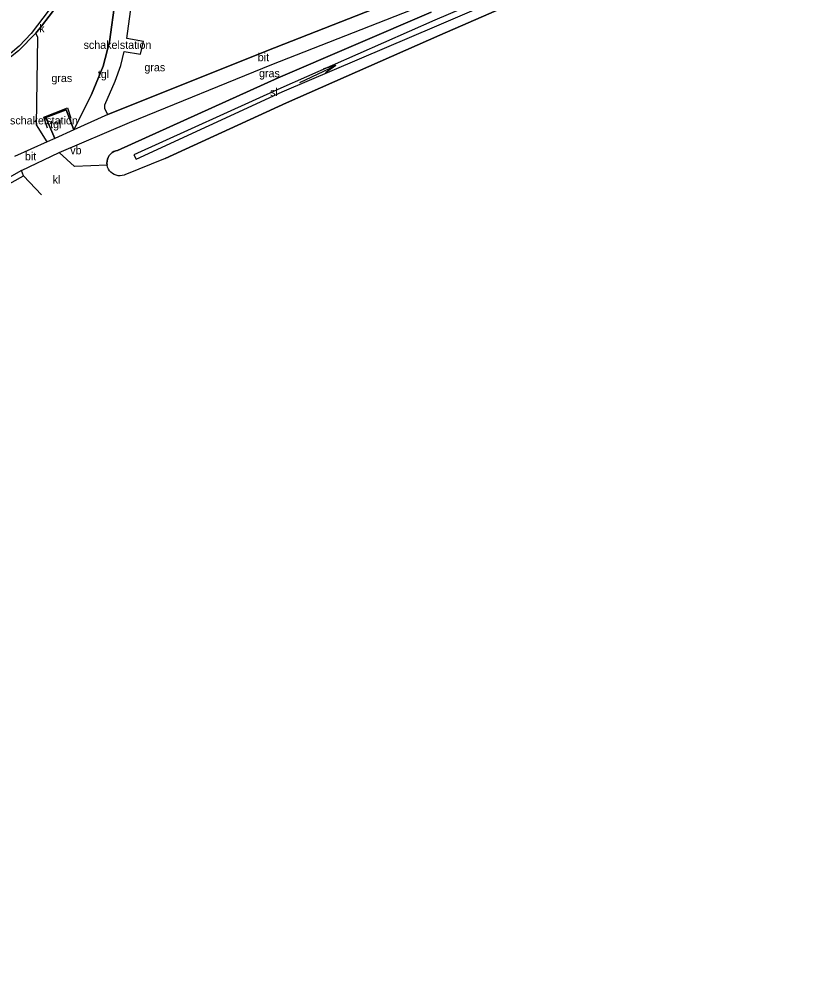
# Model space of a CAD drawing. Extents: x 154825 to 158680, y 370717 to 378075.
# Drawn here: x 156908.2 to 157007.2, y 372365.6 to 372483.5 of the extents above; entities that cross this region are included whole.
import ezdxf

# ---------------------------------------------------------------- set-up
doc = ezdxf.new("R2010")
doc.units = 0
for name, color, linetype in [('bitumenverharding(vs)', 7, 'Continuous'), ('grazige vegetatie(vs)', 7, 'Continuous'), ('hekwerkinsteek', 7, 'Continuous'), ('insteek sloot', 7, 'Continuous'), ('kantstreep', 7, 'Continuous'), ('klinkerverharding(vs)', 7, 'Continuous'), ('kolk', 7, 'Continuous'), ('maaiveldlijn algemeen - gesloten verharding', 7, 'Continuous'), ('maaiveldlijn algemeen - verharding algemeen', 7, 'Continuous'), ('palenrij', 7, 'Continuous'), ('schakelstation(vs)', 7, 'Continuous'), ('Sloot bodem', 7, 'Continuous'), ('sloot(vs)', 7, 'Continuous'), ('stroomrichting  watergangen', 7, 'Continuous'), ('tegelverh(vs)', 7, 'Continuous'), ('verkeersb_z kabel', 7, 'Continuous'), ('vlak_Grazige_vegetatie', 7, 'Continuous')]:
    doc.layers.add(name, color=color, linetype=linetype)

msp = doc.modelspace()

# ---------------------------------------------------------------- linework, layer by layer
at = {"layer": 'hekwerkinsteek'}
msp.add_lwpolyline([(156926.48, 372466.07), (156941.63, 372473), (156960.78, 372481.46), (156976.59, 372488.39), (156983.26, 372491.21)], dxfattribs=at)
at = {"layer": 'insteek sloot'}
msp.add_lwpolyline([(156926.48, 372466.07), (156921.43, 372464.01), (156921.35, 372463.98), (156921.11, 372463.91), (156920.86, 372463.88), (156920.61, 372463.9), (156920.36, 372463.95), (156920.12, 372464.04), (156919.9, 372464.17), (156919.71, 372464.33), (156919.54, 372464.52), (156919.4, 372464.73), (156919.3, 372464.96), (156919.23, 372465.21), (156919.21, 372465.46), (156919.22, 372465.71), (156919.28, 372465.96), (156919.37, 372466.19), (156919.5, 372466.41), (156919.66, 372466.61), (156919.85, 372466.78), (156920.06, 372466.91), (156920.3, 372467.01), (156920.54, 372467.07), (156940.59, 372476.12), (156959.72, 372484.32)], dxfattribs=at)
at = {"layer": 'kantstreep'}
msp.add_lwpolyline([(156912, 372484.63), (156909.76, 372481.66), (156908.24, 372480.1), (156906.59, 372478.67), (156904.7, 372477.42), (156902.73, 372476.3), (156901.13, 372475.39), (156899.83, 372474.44), (156898.3, 372472.87), (156897.08, 372471.22), (156894.54, 372467.02), (156892.73, 372464.17), (156889.8, 372459.96), (156887.24, 372457.64), (156884.63, 372455.47), (156876.12, 372449.06)], dxfattribs=at)
at = {"layer": 'maaiveldlijn algemeen - gesloten verharding'}
for points in [[(156919.34, 372471.53), (156939.19, 372479.51), (156958.63, 372487.15), (156986.56, 372498.21), (157006.17, 372506)], [(156913.23, 372466.8), (156922.02, 372470.54), (156939.79, 372477.79), (156959.27, 372485.43), (156987.12, 372496.58), (157007.18, 372504.38)], [(156920.47, 372488.95), (156918.9, 372488.58), (156916.79, 372487.72), (156914.53, 372486.34), (156912.93, 372485.08), (156911.05, 372482.6), (156910.32, 372481.71)], [(156910.32, 372481.71), (156908.15, 372479.51), (156906.33, 372478.04), (156904.02, 372476.62), (156901.44, 372475.19)], [(156919.34, 372471.53), (156915.07, 372469.64)], [(156915.07, 372469.64), (156912.68, 372468.55)], [(156911.73, 372468.12), (156907.65, 372466.29)], [(156912.68, 372468.55), (156911.73, 372468.12)], [(156908.52, 372464.53), (156913.23, 372466.8)], [(156908.52, 372464.53), (156898.44, 372458.84), (156897.09, 372458.03), (156894.3, 372456.31), (156889.29, 372453.07), (156884.66, 372450.07), (156874.8, 372442.6), (156871.75, 372440.11), (156866.81, 372435.59), (156866.44, 372435.25), (156862.3, 372431.22), (156854.27, 372423.1), (156846.87, 372414.74), (156841.18, 372407.59), (156835.27, 372399.43), (156829.96, 372390.65), (156826.51, 372382.86), (156819.22, 372365.62)]]:
    msp.add_lwpolyline(points, dxfattribs=at)
at = {"layer": 'maaiveldlijn algemeen - verharding algemeen'}
for points in [[(156919.34, 372471.53), (156918.96, 372472.26), (156918.96, 372472.74), (156920.22, 372475.71), (156920.94, 372477.68), (156921.37, 372479.44), (156923.41, 372479.09), (156923.77, 372480.68), (156921.7, 372481.03), (156922.52, 372487.22), (156922.5, 372489.42)], [(156915.07, 372469.64), (156917.26, 372474.06), (156918.73, 372477.57), (156919.55, 372480.64), (156920.24, 372485.8), (156920.47, 372488.95)], [(156911.73, 372468.12), (156910.43, 372470.24), (156910.56, 372481.17), (156910.32, 372481.71)], [(156912.68, 372468.55), (156911.56, 372471.18), (156914.1, 372472.14), (156915.07, 372469.64)], [(156913.23, 372466.8), (156915.14, 372465.04)], [(156908.77, 372463.88), (156908.52, 372464.53)], [(156895.89, 372453.66), (156894.71, 372455.85), (156900.05, 372459.01), (156908.77, 372463.88)], [(156908.77, 372463.88), (156911.04, 372461.51)]]:
    msp.add_lwpolyline(points, dxfattribs=at)
at = {"layer": 'palenrij'}
msp.add_lwpolyline([(156911.79, 372469.83), (156911.33, 372471.22), (156914.3, 372472.38), (156914.7, 372471.08)], dxfattribs=at)
at = {"layer": 'Sloot bodem'}
msp.add_lwpolyline([(156978.71, 372489.31), (156978.31, 372489.69), (156977.43, 372490.33), (156975.94, 372490.1), (156960.19, 372483.33), (156940.95, 372474.85), (156922.55, 372466.49), (156922.86, 372465.97), (156941.11, 372474.4), (156960.43, 372482.64), (156975.96, 372489.32), (156976.63, 372489.27), (156977.34, 372488.76)], dxfattribs=at)
at = {"layer": 'stroomrichting  watergangen'}
for p, q in [((156943.29, 372475.56), (156947.81, 372477.67)), ((156947.79, 372477.68), (156946.27, 372477.27)), ((156947.81, 372477.67), (156946.52, 372476.77))]:
    msp.add_line(p, q, dxfattribs=at)
at = {"layer": 'vlak_Grazige_vegetatie'}
for points in [[(156939.19, 372479.51), (156919.34, 372471.53), (156918.96, 372472.26), (156918.96, 372472.74), (156920.22, 372475.71), (156920.94, 372477.68), (156921.37, 372479.44), (156923.41, 372479.09), (156923.77, 372480.68), (156921.7, 372481.03), (156922.52, 372487.22), (156922.5, 372489.42), (156931.25, 372491), (156943.52, 372492.25), (156955.83, 372494.03), (156970.73, 372497.04), (156982.12, 372500.22), (156993.12, 372503.95), (157003.96, 372508.09), (157006.17, 372506), (156986.56, 372498.21), (156958.63, 372487.15)], [(156917.26, 372474.06), (156915.07, 372469.64), (156914.1, 372472.14), (156911.56, 372471.18), (156912.68, 372468.55), (156911.73, 372468.12), (156910.43, 372470.24), (156910.56, 372481.17), (156910.32, 372481.71), (156911.05, 372482.6), (156912.93, 372485.08), (156914.53, 372486.34), (156916.79, 372487.72), (156918.9, 372488.58), (156920.47, 372488.95), (156920.24, 372485.8), (156919.55, 372480.64), (156918.73, 372477.57)]]:
    msp.add_lwpolyline(points, close=True, dxfattribs=at)
for points in [[(156975.94, 372490.1), (156960.19, 372483.33), (156940.95, 372474.85), (156922.55, 372466.49), (156922.86, 372465.97), (156941.11, 372474.4), (156960.43, 372482.64), (156975.96, 372489.32)], [(156976.59, 372488.39), (156960.78, 372481.46), (156941.63, 372473), (156926.48, 372466.07), (156921.43, 372464.01), (156921.35, 372463.98), (156921.11, 372463.91), (156920.86, 372463.88), (156920.61, 372463.9), (156920.36, 372463.95), (156920.12, 372464.04), (156919.9, 372464.17), (156919.71, 372464.33), (156919.54, 372464.52), (156919.4, 372464.73), (156919.3, 372464.96), (156919.23, 372465.21), (156919.21, 372465.46), (156919.22, 372465.71), (156919.28, 372465.96), (156919.37, 372466.19), (156919.5, 372466.41), (156919.66, 372466.61), (156919.85, 372466.78), (156920.06, 372466.91), (156920.3, 372467.01), (156920.54, 372467.07), (156940.59, 372476.12), (156959.72, 372484.32)], [(156959.72, 372484.32), (156940.59, 372476.12), (156920.54, 372467.07), (156920.3, 372467.01), (156920.06, 372466.91), (156919.85, 372466.78), (156919.66, 372466.61), (156919.5, 372466.41), (156919.37, 372466.19), (156919.28, 372465.96), (156919.22, 372465.71), (156919.21, 372465.46), (156919.23, 372465.21), (156915.14, 372465.04), (156913.23, 372466.8), (156922.02, 372470.54), (156939.79, 372477.79), (156959.27, 372485.43)]]:
    msp.add_lwpolyline(points, dxfattribs=at)

# ---------------------------------------------------------------- texts
at = {"layer": 'bitumenverharding(vs)'}
for p in [(156938.05, 372478.21), (156908.96, 372465.83)]:
    msp.add_text('bit', height=1, dxfattribs=at).set_placement(p)
at = {"layer": 'grazige vegetatie(vs)'}
for p in [(156923.89, 372476.95), (156912.27, 372475.6), (156938.21, 372476.21)]:
    msp.add_text('gras', height=1, dxfattribs=at).set_placement(p)
at = {"layer": 'klinkerverharding(vs)'}
msp.add_text('kl', height=1, dxfattribs=at).set_placement((156912.43, 372462.92))
at = {"layer": 'kolk'}
msp.add_text('k', height=1, dxfattribs=at).set_placement((156910.76, 372481.8))
at = {"layer": 'schakelstation(vs)'}
for p in [(156916.29, 372479.75), (156907.1, 372470.31)]:
    msp.add_text('schakelstation', height=1, dxfattribs=at).set_placement(p)
at = {"layer": 'sloot(vs)'}
msp.add_text('sl', height=1, dxfattribs=at).set_placement((156939.59, 372473.84))
at = {"layer": 'tegelverh(vs)'}
for p in [(156918.07, 372476.1), (156912.11, 372469.84)]:
    msp.add_text('tgl', height=1, dxfattribs=at).set_placement(p)
at = {"layer": 'verkeersb_z kabel'}
msp.add_text('vb', height=1, dxfattribs=at).set_placement((156914.63, 372466.58))

doc.saveas('drawing.dxf')
